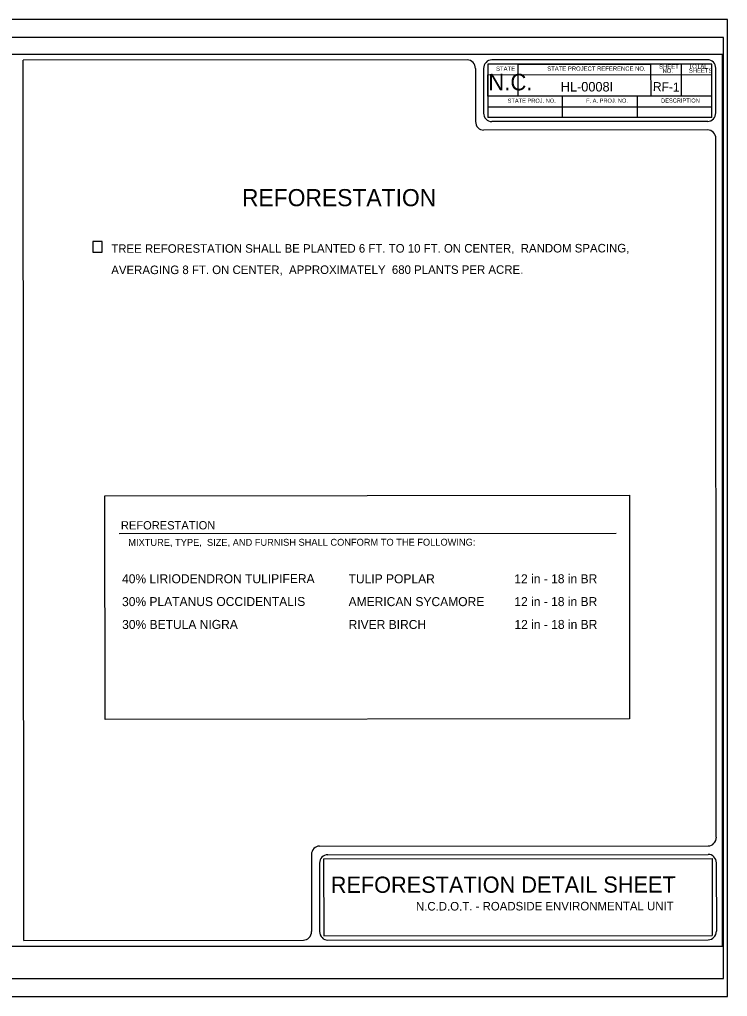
# Model space of a CAD drawing. Extents: x 816132 to 817815, y 885694 to 886789.
# Drawn here: x 817022 to 817815, y 885694 to 886789 of the extents above; entities that cross this region are included whole.
import ezdxf

# ---------------------------------------------------------------- set-up
doc = ezdxf.new("R2010")
doc.units = 0
for name, color, linetype in [('Sheet Plot Border Inside CELL', 7, 'Continuous'), ('Sheet Plot Border Outside CELL', 7, 'Continuous'), ('Silt Fence Coir Fiber Wattle Break Detail CELL', 7, 'Continuous')]:
    doc.layers.add(name, color=color, linetype=linetype)

msp = doc.modelspace()

# ---------------------------------------------------------------- linework, layer by layer
at = {"layer": 'Sheet Plot Border Inside CELL'}
msp.add_lwpolyline([(816131.6, 885693.9), (817815.1, 885693.9), (817815.1, 886788.9), (816131.6, 886788.9)], close=True, dxfattribs=at)
at = {"layer": 'Sheet Plot Border Outside CELL'}
msp.add_lwpolyline([(816144.6, 885713.9), (817810.6, 885713.9), (817810.6, 886768.9), (816144.6, 886768.9)], close=True, dxfattribs=at)
at = {"layer": 'Silt Fence Coir Fiber Wattle Break Detail CELL'}
for p, q in [((817815.1, 886788.9), (817815.1, 886788.9)), ((817523.5, 886743.6), (817025.8, 886743.2)), ((817026.5, 885756.8), (817025.8, 886743.2)), ((817792.8, 886743.8), (817550.9, 886743.6)), ((817532.6, 886734.1), (817532.7, 886674.5)), ((817541.8, 886734.1), (817541.8, 886684.1)), ((817797.4, 886739), (817546.3, 886738.9)), ((817546.3, 886738.9), (817546.4, 886679)), ((817580.6, 886738.9), (817728.9, 886739)), ((817580.6, 886703), (817580.6, 886738.9)), ((817728.9, 886739), (817729, 886703.1)), ((817797.4, 886727.1), (817797.4, 886739)), ((817802, 886684.3), (817802, 886734.3)), ((817546.3, 886726.9), (817797.4, 886727.1)), ((817546.3, 886702.9), (817546.3, 886726.9)), ((817797.4, 886703.1), (817546.3, 886702.9)), ((817630, 886703), (817580.6, 886703)), ((817630, 886679.1), (817630, 886703)), ((817729, 886703.1), (817713.7, 886703.1)), ((817713.7, 886703.1), (817713.7, 886679.1)), ((817797.4, 886691.2), (817797.4, 886703.1)), ((817546.4, 886691), (817797.4, 886691.2)), ((817797.4, 886679.2), (817546.4, 886679)), ((817792.9, 886674.7), (817550.9, 886674.5)), ((817792.9, 886665.1), (817541.8, 886664.9)), ((817802.6, 885872.3), (817802, 886655.6)), ((817133.1, 886212.7), (817690.3, 886213.1)), ((817357.9, 885862.4), (817793.5, 885862.7)), ((817348.7, 885852.8), (817348.8, 885766.6)), ((817362.4, 885848), (817798, 885848.4)), ((817362.4, 885848), (817362.5, 885761.8)), ((817367, 885852.8), (817793.5, 885853.1)), ((817798, 885848.4), (817798.1, 885762.2)), ((817357.9, 885843.2), (817357.9, 885766.6)), ((817802.6, 885843.6), (817802.7, 885767)), ((817026.5, 885756.8), (817339.7, 885757)), ((817362.5, 885761.8), (817798.1, 885762.2)), ((817367.1, 885757), (817793.5, 885757.4))]:
    msp.add_line(p, q, dxfattribs=at)
for points in [[(817809.4, 886749.8), (816263.4, 886749.8), (816263.4, 885750.3), (817809.4, 885750.3)], [(817114.2, 886540.1), (817103.6, 886540.1), (817103.6, 886528.1), (817114.2, 886528.1)], [(817117.2, 886255.2), (817705.2, 886255.7), (817705.4, 886004.9), (817117.4, 886004.4)]]:
    msp.add_lwpolyline(points, close=True, dxfattribs=at)
msp.add_lwpolyline([(817797.4, 886679.2), (817797.4, 886739), (817763.2, 886739), (817763.2, 886703.1)], dxfattribs=at)
for centre, major_axis, start_param, end_param in [((817523.5, 886734), (0, 9.58), 4.713138, 6.283935), ((817550.9, 886734.1), (0, 9.58), 0.000749, 1.571546), ((817792.8, 886734.3), (0, 9.58), 4.713138, 6.283935), ((817550.9, 886684.1), (0, -9.58), 4.713138, 6.283935), ((817792.9, 886684.3), (0, 9.58), 3.142342, 4.713138), ((817541.8, 886674.5), (0, -9.58), 4.713138, 6.283935), ((817792.9, 886655.6), (0, 9.58), 4.713138, 6.283935), ((817793.5, 885872.3), (0, -9.58), 0.000749, 1.571546), ((817357.9, 885852.8), (0, -9.58), 3.142342, 4.713138), ((817367, 885843.2), (0, 9.58), 0.000749, 1.571546), ((817793.5, 885843.6), (0, 9.58), 4.713138, 6.283935), ((817339.7, 885766.6), (0, 9.58), 3.142342, 4.713138), ((817367.1, 885766.6), (0, -9.58), 4.713138, 6.283935), ((817793.5, 885767), (0, 9.58), 3.142342, 4.713138)]:
    msp.add_ellipse(centre, major_axis=major_axis, ratio=0.953323, start_param=start_param, end_param=end_param, dxfattribs=at)

# ---------------------------------------------------------------- texts
for s, height, rotation, p in [('STATE', 4.79, 0.045, (817555.7, 886731.4)), ('STATE PROJECT REFERENCE NO.', 4.788, 0.045, (817613.1, 886731.5)), ('SHEET', 4.79, 0.045, (817738.5, 886733.7)), ('NO.', 4.79, 0.045, (817742.3, 886729)), ('TOTAL', 4.79, 0.045, (817771.5, 886734.1)), ('SHEETS', 4.79, 0.045, (817771.8, 886729.3)), ('N.C.', 18.53, 0.045, (817547, 886709.5)), ('HL-0008I', 10.68, 0.045, (817628.2, 886708.2)), ('RF-1', 10.04, 358.6121, (817731.4, 886708.8)), ('STATE PROJ. NO.', 4.597, 0.045, (817568.7, 886695.6)), ('F. A. PROJ. NO.', 4.597, 0.045, (817656.6, 886695.7)), ('DESCRIPTION', 4.597, 0.045, (817740.7, 886695.8)), ('REFORESTATION', 19.155, 360, (817270.9, 886579.7)), ('TREE REFORESTATION SHALL BE PLANTED 6 FT. TO 10 FT. ON CENTER,  RANDOM SPACING,', 9.577, 0.045, (817124.4, 886527.4)), ('AVERAGING 8 FT. ON CENTER,  APPROXIMATELY  680 PLANTS PER ACRE. ', 9.577, 0.045, (817124.4, 886503.5)), ('REFORESTATION ', 9.309, 0.045, (817135.2, 886217.3)), ('MIXTURE, TYPE,  SIZE, AND FURNISH SHALL CONFORM TO THE FOLLOWING:', 7.758, 0.045, (817143.5, 886198.9)), ('40% LIRIODENDRON TULIPIFERA', 10.084, 0.045, (817136.5, 886157)), ('TULIP POPLAR', 10.084, 360, (817390.4, 886157)), ('12 in - 18 in BR', 10.084, 0.045, (817576.2, 886157)), ('30% PLATANUS OCCIDENTALIS', 10.084, 0.045, (817136.5, 886131.4)), ('AMERICAN SYCAMORE', 10.084, 360, (817390.4, 886131.4)), ('12 in - 18 in BR', 10.084, 0.045, (817576.2, 886131.4)), ('30% BETULA NIGRA', 10.084, 0.045, (817136.6, 886105.8)), ('RIVER BIRCH', 10.084, 360, (817390.4, 886105.8)), ('12 in - 18 in BR', 10.084, 0.045, (817576.3, 886105.8)), ('REFORESTATION DETAIL SHEET', 18.196, 0.045, (817370.4, 885810)), ('N.C.D.O.T. - ROADSIDE ENVIRONMENTAL UNIT', 9.577, 0.045, (817465.9, 885790.2))]:
    msp.add_text(s, height=height, rotation=rotation, dxfattribs=at).set_placement(p)

doc.saveas('drawing.dxf')
